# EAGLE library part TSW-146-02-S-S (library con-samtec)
THROUGH-HOLE .025" SQ POST HEADER Source: Samtec TSW.pdf
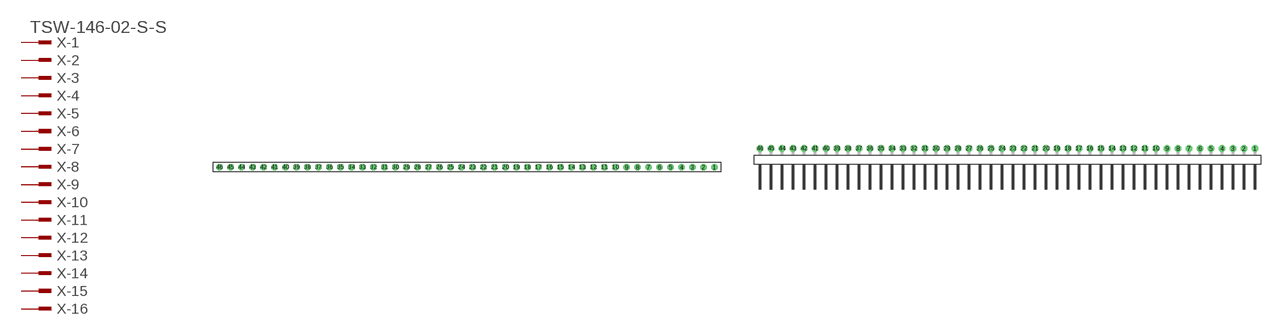
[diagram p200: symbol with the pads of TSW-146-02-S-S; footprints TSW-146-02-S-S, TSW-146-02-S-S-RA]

Designator prefix X; gates -1=MPINV -2=MPIN -3=MPIN -4=MPIN -5=MPIN -6=MPIN -7=MPIN -8=MPIN -9=MPIN -10=MPIN -11=MPIN -12=MPIN -13=MPIN -14=MPIN -15=MPIN -16=MPIN -17=MPIN -18=MPIN -19=MPIN -20=MPIN -21=MPIN -22=MPIN -23=MPIN -24=MPIN -25=MPIN -26=MPIN -27=MPIN -28=MPIN -29=MPIN -30=MPIN -31=MPIN -32=MPIN -33=MPIN -34=MPIN -35=MPIN -36=MPIN -37=MPIN -38=MPIN -39=MPIN -40=MPIN -41=MPIN -42=MPIN -43=MPIN -44=MPIN -45=MPIN -46=MPIN

## TSW-146-02-S-S (OC_FARNELL: unknown; OC_NEWARK: unknown)  [TSW-146-02-S-S]
1  -1:1  pas
2  -2:1  pas
3  -3:1  pas
4  -4:1  pas
5  -5:1  pas
6  -6:1  pas
7  -7:1  pas
8  -8:1  pas
9  -9:1  pas
10  -10:1  pas
11  -11:1  pas
12  -12:1  pas
13  -13:1  pas
14  -14:1  pas
15  -15:1  pas
16  -16:1  pas
17  -17:1  pas
18  -18:1  pas
19  -19:1  pas
20  -20:1  pas
21  -21:1  pas
22  -22:1  pas
23  -23:1  pas
24  -24:1  pas
25  -25:1  pas
26  -26:1  pas
27  -27:1  pas
28  -28:1  pas
29  -29:1  pas
30  -30:1  pas
31  -31:1  pas
32  -32:1  pas
33  -33:1  pas
34  -34:1  pas
35  -35:1  pas
36  -36:1  pas
37  -37:1  pas
38  -38:1  pas
39  -39:1  pas
40  -40:1  pas
41  -41:1  pas
42  -42:1  pas
43  -43:1  pas
44  -44:1  pas
45  -45:1  pas
46  -46:1  pas

## TSW-146-02-S-S-RA (OC_FARNELL: unknown; OC_NEWARK: unknown)  [TSW-146-02-S-S-RA]
Pads as for TSW-146-02-S-S

## Footprint TSW-146-02-S-S (pad centres in mm)
THROUGH-HOLE .025" SQ POST HEADER Source: Samtec TSW.pdf
drill 1 pad 1.5 octagon: 1 57.15,0; 2 54.61,0; 3 52.07,0; 4 49.53,0; 5 46.99,0; 6 44.45,0; 7 41.91,0; 8 39.37,0; 9 36.83,0; 10 34.29,0; 11 31.75,0; 12 29.21,0; 13 26.67,0; 14 24.13,0; 15 21.59,0; 16 19.05,0; 17 16.51,0; 18 13.97,0; 19 11.43,0; 20 8.89,0; 21 6.35,0; 22 3.81,0; 23 1.27,0; 24 -1.27,0; 25 -3.81,0; 26 -6.35,0; 27 -8.89,0; 28 -11.43,0; 29 -13.97,0; 30 -16.51,0; 31 -19.05,0; 32 -21.59,0; 33 -24.13,0; 34 -26.67,0; 35 -29.21,0; 36 -31.75,0; 37 -34.29,0; 38 -36.83,0; 39 -39.37,0; 40 -41.91,0; 41 -44.45,0; 42 -46.99,0; 43 -49.53,0; 44 -52.07,0; 45 -54.61,0; 46 -57.15,0

## Footprint TSW-146-02-S-S-RA (pad centres in mm)
THROUGH-HOLE .025" SQ POST HEADER Source: Samtec TSW.pdf
drill 1 pad 1.5 octagon: 1 57.15,1.524; 2 54.61,1.524; 3 52.07,1.524; 4 49.53,1.524; 5 46.99,1.524; 6 44.45,1.524; 7 41.91,1.524; 8 39.37,1.524; 9 36.83,1.524; 10 34.29,1.524; 11 31.75,1.524; 12 29.21,1.524; 13 26.67,1.524; 14 24.13,1.524; 15 21.59,1.524; 16 19.05,1.524; 17 16.51,1.524; 18 13.97,1.524; 19 11.43,1.524; 20 8.89,1.524; 21 6.35,1.524; 22 3.81,1.524; 23 1.27,1.524; 24 -1.27,1.524; 25 -3.81,1.524; 26 -6.35,1.524; 27 -8.89,1.524; 28 -11.43,1.524; 29 -13.97,1.524; 30 -16.51,1.524; 31 -19.05,1.524; 32 -21.59,1.524; 33 -24.13,1.524; 34 -26.67,1.524; 35 -29.21,1.524; 36 -31.75,1.524; 37 -34.29,1.524; 38 -36.83,1.524; 39 -39.37,1.524; 40 -41.91,1.524; 41 -44.45,1.524; 42 -46.99,1.524; 43 -49.53,1.524; 44 -52.07,1.524; 45 -54.61,1.524; 46 -57.15,1.524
